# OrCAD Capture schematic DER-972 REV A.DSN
size Custom; title: DER 972; rev: A
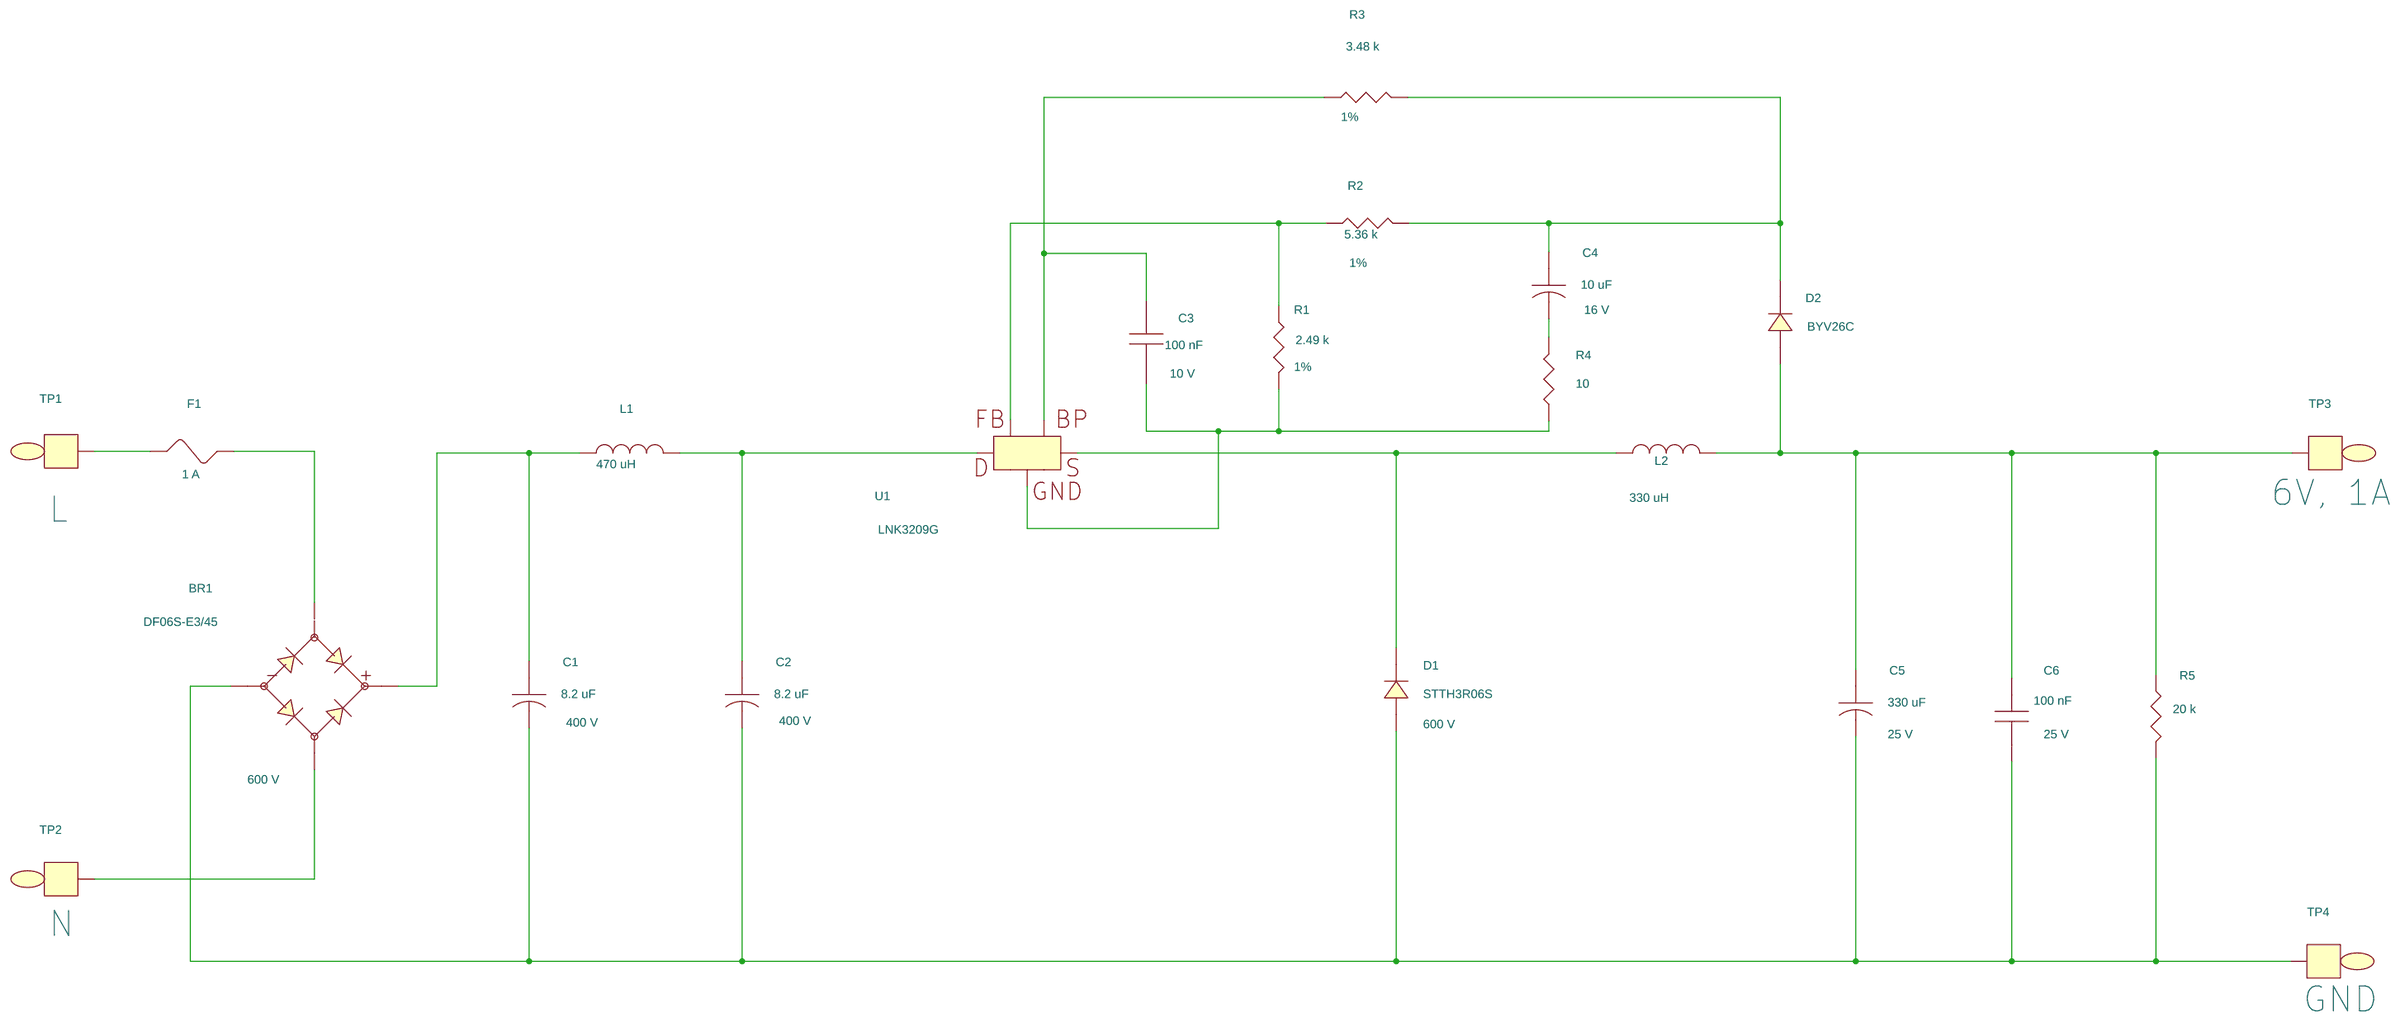
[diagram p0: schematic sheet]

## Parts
BR1  DF06S-E3/45  [pismddfs]
C1  8.2 uF  [pipolcapclyd320ls140030]
C2  8.2 uF  [pipolcapclyd320ls140030]
C3  100 nF  [pismc0805]
C4  10 uF  [pipolcapclyd200ls80030]
C5  330 uF  [pipolcapclyd320ls140030]
C6  100 nF  [pismc1206]
D1  STTH3R06S  [pismdo214ab12]
D2  BYV26C  [pidv200x150x040sod57]
F1  1 A  [pi_rst_microfuse]
L1  470 uH  [pichoketokinvd345h453ls197d030]
L2  330 uH  [pichokeCoilCrftd13p3h16ls5d043]
R1  2.49 k  [pismr0603]
R2  5.36 k  [pismr0603]
R3  3.48 k  [pismr0603]
R4  10  [pismr0603]
R5  20 k  [pismr0805]
TP1  WHT  [pitpkeystone125x125]
TP2  BLK  [pitpkeystone125x125]
TP3  RED  [pitpkeystone100x100]
TP4  BLK  [pitpkeystone100x100]
U1  LNK3209G  [piicsmd8cshort567IPC]

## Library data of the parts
BR1 = DIODE_BRIDGE_+-~~: Disp_Voltage: 600 V; Part Number: 15-00281-00
C1 C2 = CAP_POL: ALT_SYMBOLS: pipolcapclyd320ls140030670h; Disp_Voltage: 400 V; FPLIST: pipolcapclyd320ls140030,pipolcapclyd320ls140030430h,pipolcapclyd320ls140030670h; Part Number: 20-08899-00; Voltage: 400 V
C3 = CAP_NP: Disp_Voltage: 10 V; Part Number: 20-01399-00; Voltage: 10 V
C4 = CAP_POL: ALT_SYMBOLS: pipolcapclyd200ls80030h; Disp_Voltage: 16 V; FPLIST: pipolcapclyd200ls80030,pipolcapclyd200ls80030h; Part Number: 20-00649-00; Voltage: 16 V
C5 = CAP_POL: Disp_Voltage: 25 V; FPLIST: pipolcapclyd320ls140030,pipolcapclyd320ls140030430h; Part Number: 20-00029-00; Voltage: 25 V
C6 = CAP_NP: Disp_Voltage: 25 V; Part Number: 20-08743-00; Voltage: 25 V
D1 = DIODE: Disp_Voltage: 600 V; Part Number: 15-00827-00
D2 = DIODE: ALT_SYMBOLS: pidax425x150040sod57,pidv200x150x040sod57r; FPLIST: pidv200x150x040sod57,pidax425x150040sod57,pidv200x150x040sod57r; Part Number: 15-00128-00
F1 = FUSE: ALT_SYMBOLS: pirstmicrofusehoz; FPLIST: pi_rst_microfuse,pirstmicrofusehoz; Part Number: 40-00053-00
L1 = INDUCTOR: ALT_SYMBOLS: pichoketokinvd345h453ls197d030H; FPLIST: pichoketokinvd345h453ls197d030,pichoketokinvd345h453ls197d030H; Part Number: 30-00024-00
L2 = INDUCTOR: Part Number: 30-00530-00
R1 = R: Disp_Tol: 1%; Part Number: 05-01116-00
R2 = R: Disp_Tol: 1%; Part Number: 05-01148-00
R3 = R: Disp_Tol: 1%; Part Number: 05-01130-00
R4 = R: Part Number: 05-01640-00
R5 = R: Part Number: 05-01550-00
TP1 = TESTPOINT: Part Number: 35-00044-00
TP2 = TESTPOINT: Part Number: 35-00042-00
TP3 = TESTPOINT: Part Number: 35-00080-00
TP4 = TESTPOINT: ALT_SYMBOLS: TP_TH_CR2_D1_1; Part Number: 35-00079-00
U1 = LNK32XX_8G: Part Number: 10-01354-00

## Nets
N4183667: C2.1 L1.2 U1.4
N4183685: BR1.2 C1.2 C2.2 C5.2 C6.2 D1.2 R5.2 TP4.1
N4184589: C3.1 R3.1 U1.1
N4184987: D1.1 L2.1 U1.5
N4185002: C5.1 C6.1 D2.2 L2.2 R5.1 TP3.1
N4185015: C4.1 D2.1 R2.2 R3.2
N4189997: F1.2 TP1.1
N4191135: BR1.3 F1.1
N4191219: BR1.1 C1.1 L1.1
N4191500: BR1.4 TP2.1
N4228387: R1.1 R2.1 U1.2
N4235479: C3.2 R1.2 R4.1 U1.8
N4237461: C4.2 R4.2

Not connected (* = marked no-connect by the designer): U1 6 7

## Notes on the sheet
- L
- 6V, 1A
- N
- GND
